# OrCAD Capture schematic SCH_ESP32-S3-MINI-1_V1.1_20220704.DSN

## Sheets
1 01_DesignBlock: title: <ESP32-S3-MINI-1>; rev: V1.1; note: <01_DesignBlock>
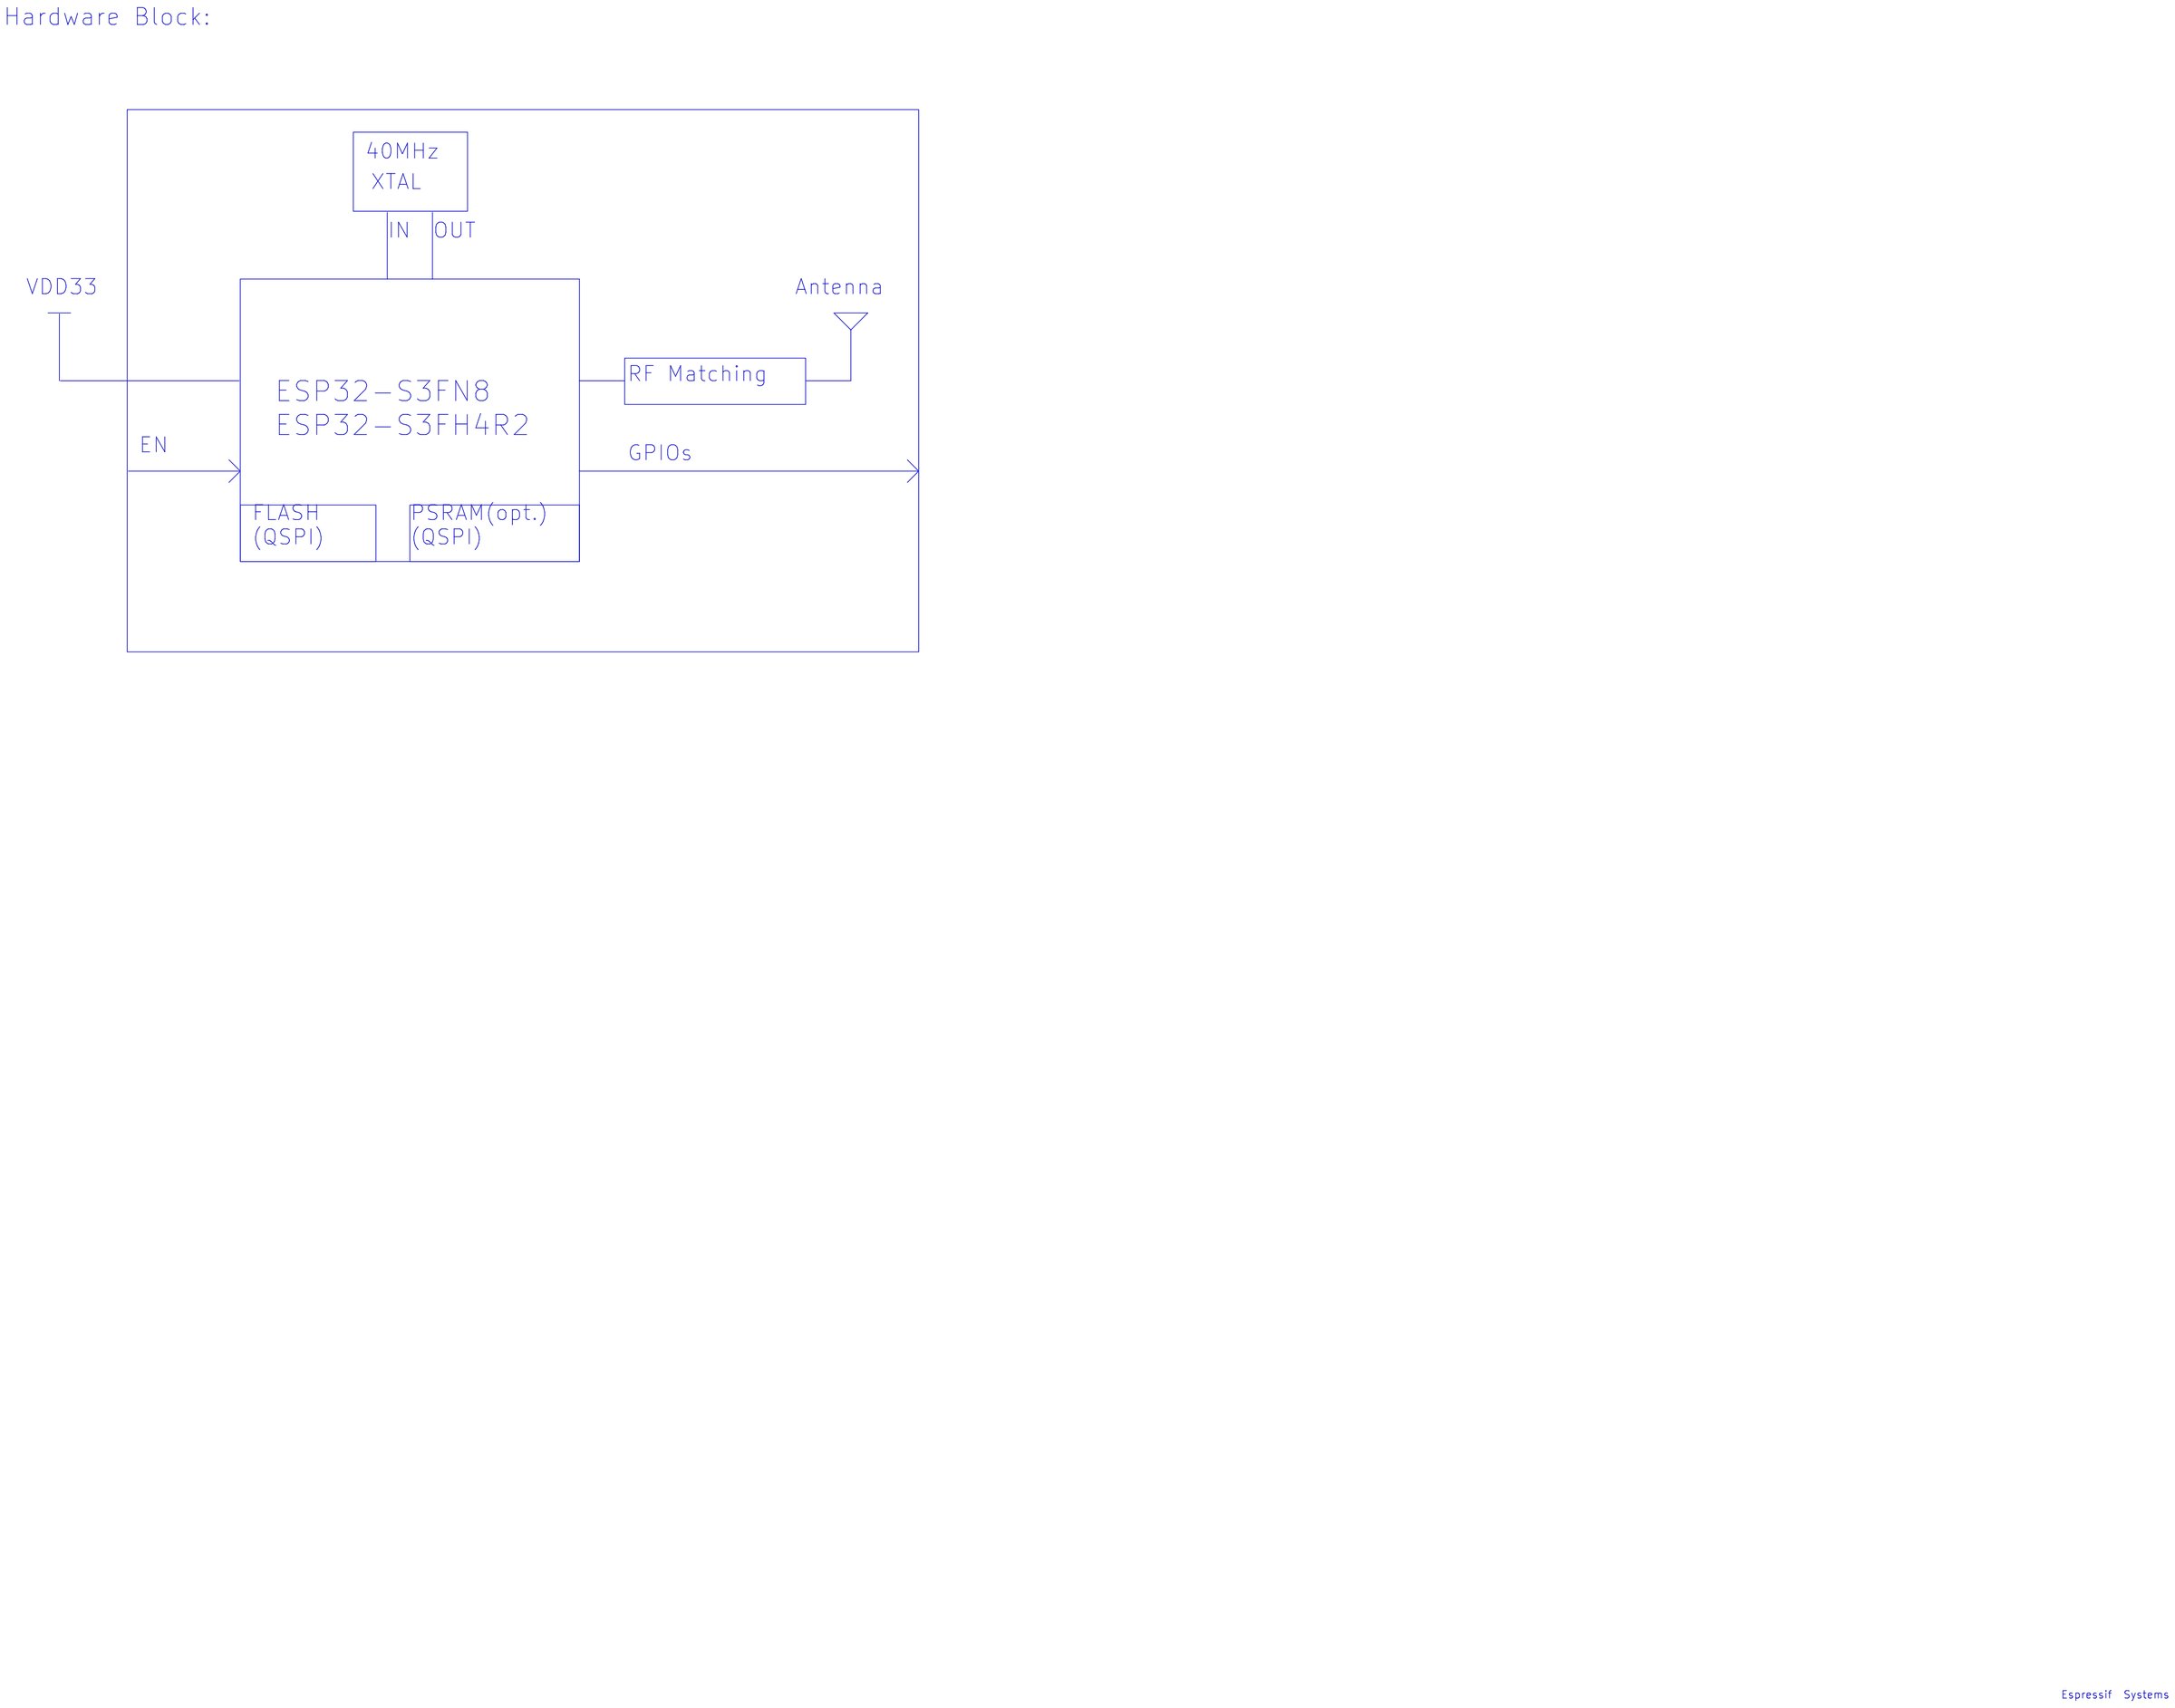
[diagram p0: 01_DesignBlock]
2 02_ESP32-S3-MINI-1: size A3; note: <02_ESP32-S3-MINI-1>
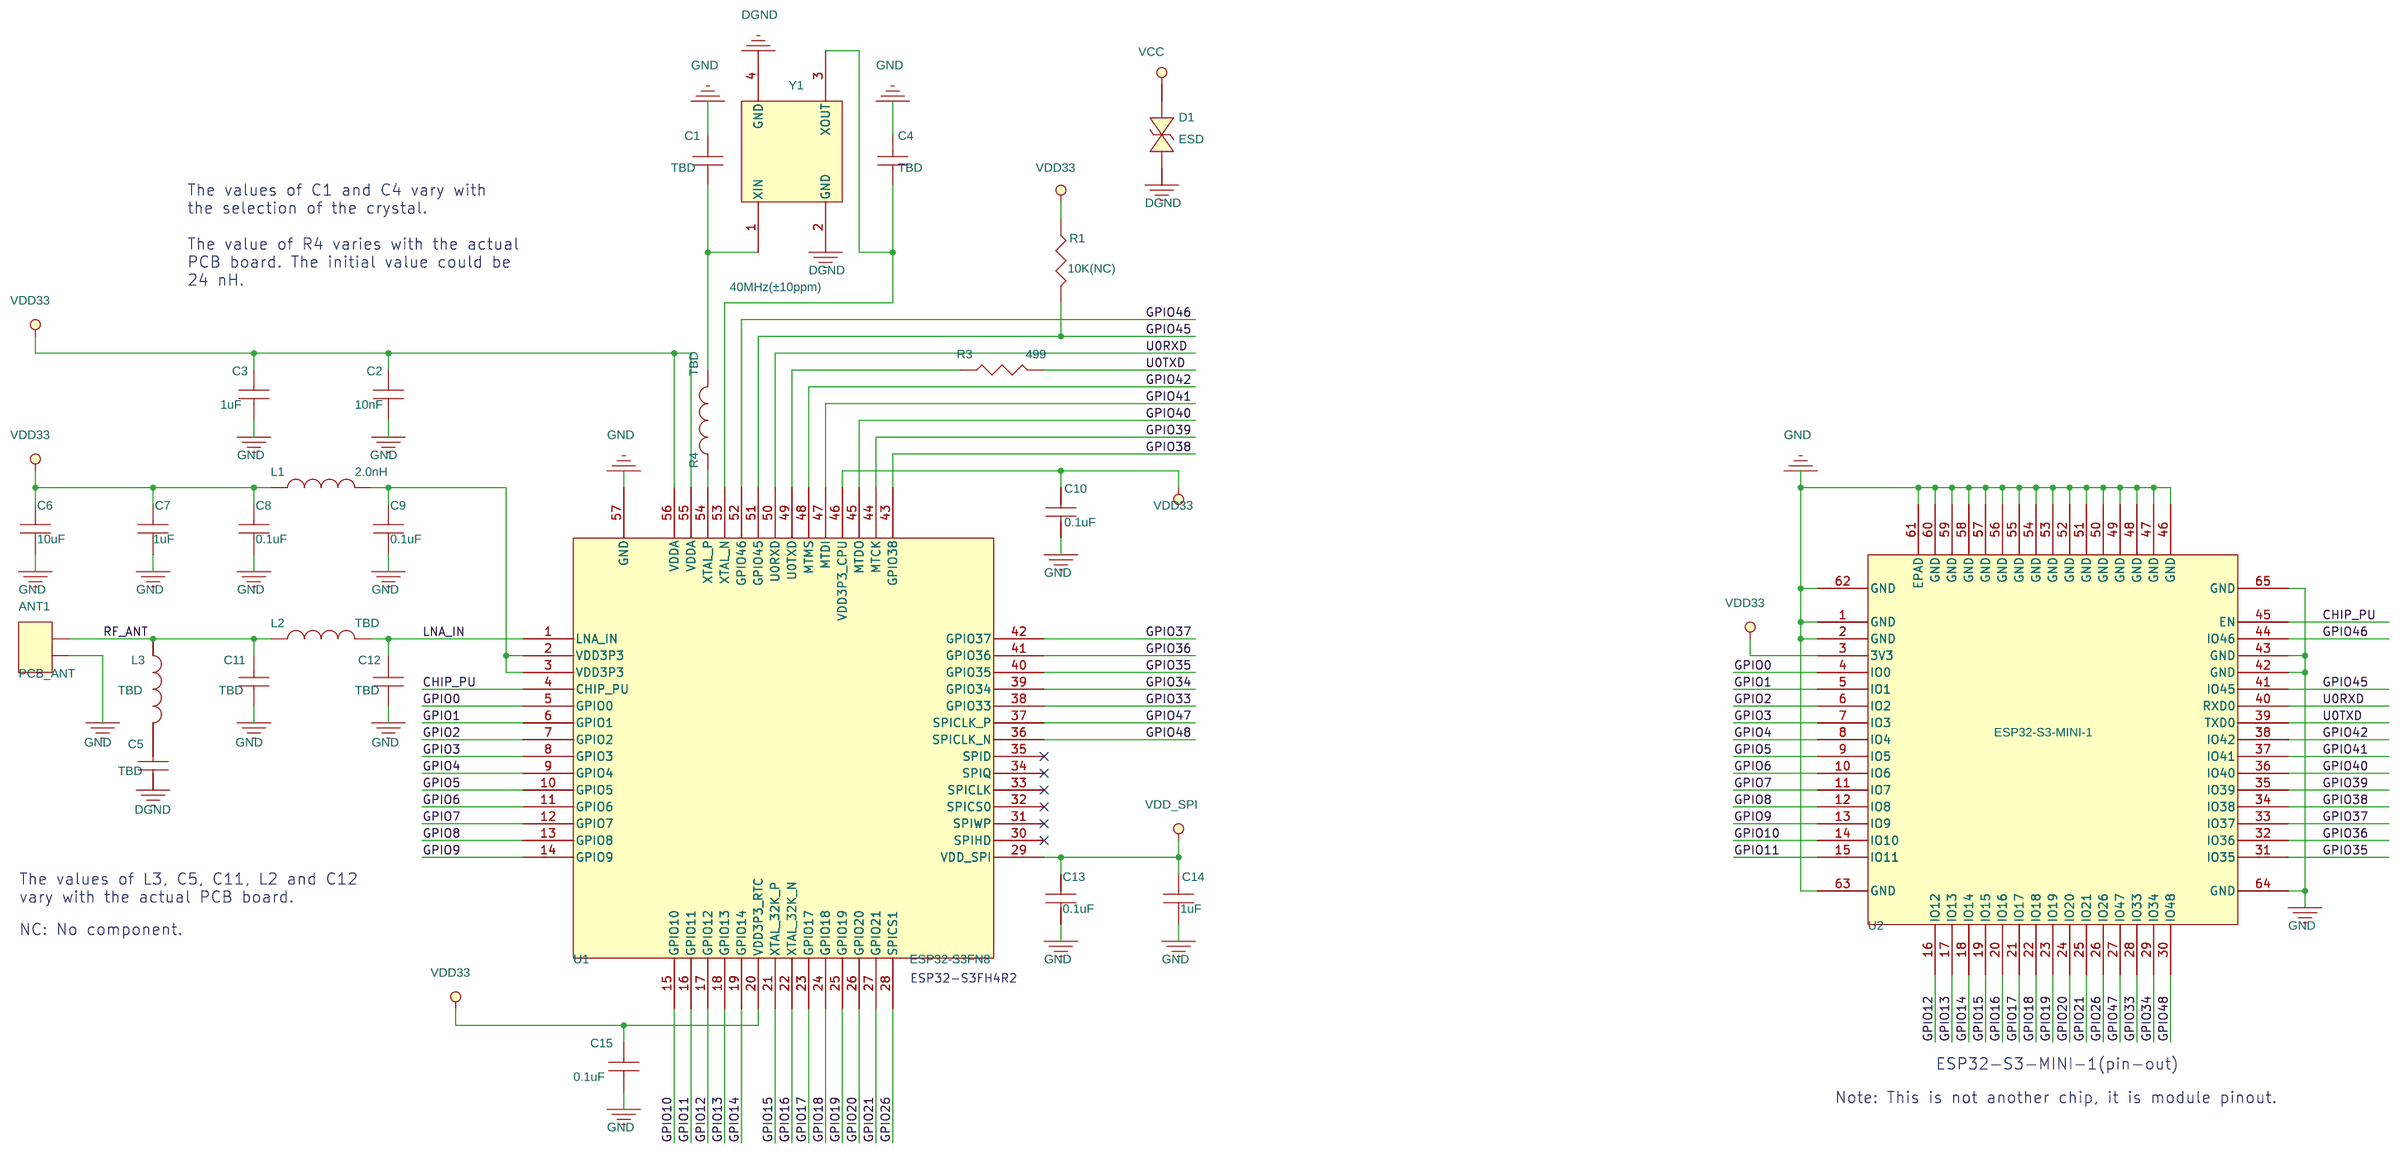
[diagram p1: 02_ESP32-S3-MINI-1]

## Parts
ANT1  PCB_ANT  [MINI-ANT-TYPES-H]
C1  TBD  [C0201]
C2  10nF  [C0201]
C3  1uF  [C0201]
C4  TBD  [C0201]
C5  TBD  [C0201]
C6  10uF  [C0402]
C7  1uF  [C0201]
C8  0.1uF  [C0201]
C9  0.1uF  [C0201]
C10  0.1uF  [C0201]
C11  TBD  [C0201]
C12  TBD  [C0201]
C13  0.1uF  [C0201]
C14  1uF  [C0201]
C15  0.1uF  [C0201]
D1  ESD  [SOD882]
L1  2.0nH  [L0201]
L2  TBD  [L0201]
L3  TBD  [L0201]
R1  10K(NC)  [R0201]
R3  499  [R0201]
R4  TBD  [L0201]
U1  ESP32-S3FN8  [QFN56_0P4_7]
U2  ESP32-S3-MINI-1  [QFN60_0P85_14_MINI]
Y1  40MHz(±10ppm)  [XTAL3225]

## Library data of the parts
ANT1 = PCB_ANT
C1-C15 = CAP
D1 = DIODE_BI-DIR_TRIG
L1-L3 R4 = Inductor
R1 R3 = RESISTOR_0
U1 = ESP32-S3_New
U2 = ESP32-S3-MINI
Y1 = X1_1

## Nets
GND: ANT1.2 C1.2 C2.2 C3.2 C4.2 C5.1 C6.2 C7.2 C8.2 C9.2 C10.2 C11.1 C12.1 C13.2 C14.2 C15.2 D1.2 U1.57(GND) U2.1(GND) U2.2(GND) U2.42(GND) U2.43(GND) U2.46(GND) U2.47(GND) U2.48(GND) U2.49(GND) U2.50(GND) U2.51(GND) U2.52(GND) U2.53(GND) U2.54(GND) U2.55(GND) U2.56(GND) U2.57(GND) U2.58(GND) U2.59(GND) U2.60(GND) U2.61(EPAD) U2.62(GND) U2.63(GND) U2.64(GND) U2.65(GND) Y1.2(GND) Y1.4(GND)
VDD33: C2.1 C3.1 C6.1 C7.1 C8.1 C10.1 C15.1 D1.1 L1.1 R1.1 U1.20(VDD3P3_RTC) U1.46(VDD3P3_CPU) U1.55(VDDA) U1.56(VDDA) U2.3(3V3)
VDD_SPI: C13.1 C14.1 U1.29(VDD_SPI)
CHIP_PU: U1.4(CHIP_PU) U2.45(EN)
GPIO0: U1.5(GPIO0) U2.4(IO0)
GPIO1: U1.6(GPIO1) U2.5(IO1)
GPIO2: U1.7(GPIO2) U2.6(IO2)
GPIO3: U1.8(GPIO3) U2.7(IO3)
GPIO4: U1.9(GPIO4) U2.8(IO4)
GPIO5: U1.10(GPIO5) U2.9(IO5)
GPIO6: U1.11(GPIO6) U2.10(IO6)
GPIO7: U1.12(GPIO7) U2.11(IO7)
GPIO8: U1.13(GPIO8) U2.12(IO8)
GPIO9: U1.14(GPIO9) U2.13(IO9)
GPIO10: U1.15(GPIO10) U2.14(IO10)
GPIO11: U1.16(GPIO11) U2.15(IO11)
GPIO12: U1.17(GPIO12) U2.16(IO12)
GPIO13: U1.18(GPIO13) U2.17(IO13)
GPIO14: U1.19(GPIO14) U2.18(IO14)
GPIO15: U1.21(XTAL_32K_P) U2.19(IO15)
GPIO16: U1.22(XTAL_32K_N) U2.20(IO16)
GPIO17: U1.23(GPIO17) U2.21(IO17)
GPIO18: U1.24(GPIO18) U2.22(IO18)
GPIO19: U1.25(GPIO19) U2.23(IO19)
GPIO20: U1.26(GPIO20) U2.24(IO20)
GPIO21: U1.27(GPIO21) U2.25(IO21)
GPIO26: U1.28(SPICS1) U2.26(IO26)
GPIO33: U1.38(GPIO33) U2.28(IO33)
GPIO34: U1.39(GPIO34) U2.29(IO34)
GPIO35: U1.40(GPIO35) U2.31(IO35)
GPIO36: U1.41(GPIO36) U2.32(IO36)
GPIO37: U1.42(GPIO37) U2.33(IO37)
GPIO38: U1.43(GPIO38) U2.34(IO38)
GPIO39: U1.44(MTCK) U2.35(IO39)
GPIO40: U1.45(MTDO) U2.36(IO40)
GPIO41: U1.47(MTDI) U2.37(IO41)
GPIO42: U1.48(MTMS) U2.38(IO42)
GPIO45: R1.2 U1.51(GPIO45) U2.41(IO45)
GPIO46: U1.52(GPIO46) U2.44(IO46)
GPIO47: U1.37(SPICLK_P) U2.27(IO47)
GPIO48: U1.36(SPICLK_N) U2.30(IO48)
LNA_IN: C12.2 L2.1 U1.1(LNA_IN)
RF_ANT: ANT1.1 C11.2 L2.2 L3.1
U0RXD: U1.50(U0RXD) U2.40(RXD0)
U0TXD: R3.2 U2.39(TXD0)
N16981226: C9.1 L1.2 U1.2(VDD3P3) U1.3(VDD3P3)
N16989817: C4.1 U1.53(XTAL_N) Y1.3(XOUT)
N16993150: R3.1 U1.49(U0TXD)
N17123375: C1.1 R4.1 Y1.1(XIN)
N17154365: R4.2 U1.54(XTAL_P)
N17163000: C5.2 L3.2

Not connected (* = marked no-connect by the designer): U1 30(SPIHD)* 31(SPIWP)* 32(SPICS0)* 33(SPICLK)* 34(SPIQ)* 35(SPID)*

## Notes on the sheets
sheet 1
- Hardware Block:
- 40MHz
- XTAL
- IN
- OUT
- VDD33
- Antenna
- RF Matching
- ESP32-S3FN8
- ESP32-S3FH4R2
- EN
- GPIOs
- FLASH
  (QSPI)
- PSRAM(opt.)
  (QSPI)
- Espressif  Systems
sheet 2
- The values of C1 and C4 vary with
  the selection of the crystal.
  The value of R4 varies with the actual
  PCB board. The initial value could be
  24 nH.
- The values of L3, C5, C11, L2 and C12
  vary with the actual PCB board.
- NC: No component.
- ESP32-S3FH4R2
- ESP32-S3-MINI-1(pin-out)
- Note: This is not another chip, it is module pinout.
